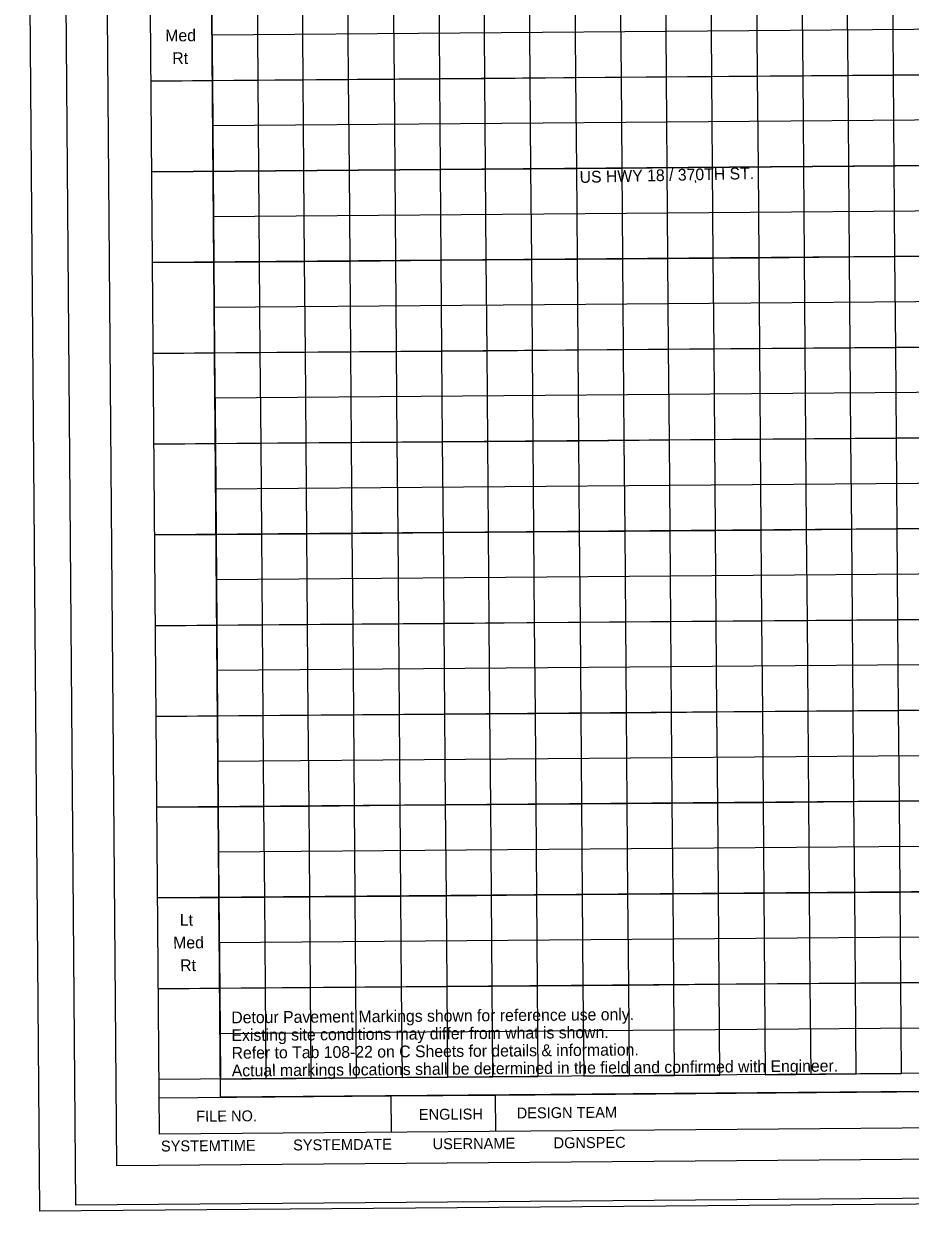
# Model space of a CAD drawing. Extents: x 11670159 to 11702568, y 9558247 to 9571922.
# Drawn here: x 11683828 to 11685781, y 9566402 to 9569018 of the extents above; entities that cross this region are included whole.
import ezdxf

# ---------------------------------------------------------------- set-up
doc = ezdxf.new("R2010")
doc.units = 0
for name, color, linetype in [('dsnNonPlotable', 7, 'Continuous'), ('DsnShtDBGLtRtTextLower', 7, 'Continuous'), ('DsnShtDBGLtRtTextUpper', 7, 'Continuous'), ('DsnShtDBGMedTextLower', 7, 'Continuous'), ('DsnShtDBGMedTextUpper', 7, 'Continuous'), ('DsnShtHorizMidLine', 7, 'Continuous'), ('DsnShtInsideBorder', 7, 'Continuous'), ('DsnShtMajorGrid01', 7, 'Continuous'), ('DsnShtMajorGrid02', 7, 'Continuous'), ('DsnShtMajorGrid03', 7, 'Continuous'), ('DsnShtMajorGrid04', 7, 'Continuous'), ('DsnShtMajorGrid05', 7, 'Continuous'), ('DsnShtMajorGrid06', 7, 'Continuous'), ('DsnShtMajorGrid07', 7, 'Continuous'), ('DsnShtMajorGrid08', 7, 'Continuous'), ('DsnShtMajorGrid09', 7, 'Continuous'), ('DsnShtMajorGrid10', 7, 'Continuous'), ('DsnShtMajorGrid11', 7, 'Continuous'), ('DsnShtMajorGrid12', 7, 'Continuous'), ('DsnShtMinorGrid01', 7, 'Continuous'), ('DsnShtMinorGrid02', 7, 'Continuous'), ('DsnShtMinorGrid03', 7, 'Continuous'), ('DsnShtMinorGrid04', 7, 'Continuous'), ('DsnShtMinorGrid05', 7, 'Continuous'), ('DsnShtMinorGrid06', 7, 'Continuous'), ('DsnShtMinorGrid07', 7, 'Continuous'), ('DsnShtMinorGrid08', 7, 'Continuous'), ('DsnShtMinorGrid09', 7, 'Continuous'), ('DsnShtMinorGrid10', 7, 'Continuous'), ('DsnShtMinorGrid11', 7, 'Continuous'), ('DsnShtMinorGrid12', 7, 'Continuous'), ('DsnShtOutsideBorder', 7, 'Continuous'), ('DsnShtPlotIdentification', 7, 'Continuous'), ('DsnShtPlotShape', 7, 'Continuous'), ('dsnShtPlotShapeBatchPrint', 7, 'Continuous'), ('dsnTextFinalPlan', 7, 'Continuous'), ('hwyPlanSheetShape', 7, 'Continuous')]:
    doc.layers.add(name, color=color, linetype=linetype)

msp = doc.modelspace()

# ---------------------------------------------------------------- linework, layer by layer
at = {"layer": 'dsnNonPlotable'}
msp.add_line((11685307.4, 9568673.2), (11685307.5, 9568668.3), dxfattribs=at)
msp.add_lwpolyline([(11684229.4, 9570693), (11690229.2, 9570741.4), (11690261.8, 9566701.6), (11684262, 9566653.2)], close=True, dxfattribs=at)
at = {"layer": 'DsnShtHorizMidLine'}
msp.add_line((11684110.5, 9568692), (11690380.3, 9568742.6), dxfattribs=at)
at = {"layer": 'DsnShtInsideBorder'}
for p, q in [((11684636.8, 9566656.2), (11684637.4, 9566576.2)), ((11684866.8, 9566658), (11684867.4, 9566578))]:
    msp.add_line(p, q, dxfattribs=at)
at = {"layer": 'DsnShtMajorGrid01'}
for points in [[(11690394.8, 9566942.6), (11684125, 9566892.1), (11684260, 9566893.1), (11684261.7, 9566693.2), (11684461.6, 9566694.8), (11684460, 9566894.8), (11684660, 9566896.4), (11684661.6, 9566696.4), (11684861.6, 9566698), (11684860, 9566898), (11685060, 9566899.6), (11685061.6, 9566699.6), (11685261.6, 9566701.2), (11685260, 9566901.2), (11685460, 9566902.8), (11685461.6, 9566702.8), (11685661.6, 9566704.4), (11685660, 9566904.4), (11685860, 9566906.1)], [(11690396.5, 9566742.6), (11684126.7, 9566692.1)]]:
    msp.add_lwpolyline(points, dxfattribs=at)
at = {"layer": 'DsnShtMajorGrid02'}
for points in [[(11690393.2, 9567142.6), (11684123.4, 9567092.1), (11684258.4, 9567093.1), (11684260, 9566893.1), (11684460, 9566894.8), (11684458.4, 9567094.8), (11684658.4, 9567096.4), (11684660, 9566896.4), (11684860, 9566898), (11684858.4, 9567098), (11685058.4, 9567099.6), (11685060, 9566899.6), (11685260, 9566901.2), (11685258.4, 9567101.2), (11685458.4, 9567102.8), (11685460, 9566902.8), (11685660, 9566904.4), (11685658.4, 9567104.4), (11685858.4, 9567106)], [(11690394.8, 9566942.6), (11684125, 9566892.1)]]:
    msp.add_lwpolyline(points, dxfattribs=at)
at = {"layer": 'DsnShtMajorGrid03'}
for points in [[(11690391.6, 9567342.6), (11684121.8, 9567292), (11684256.8, 9567293.1), (11684258.4, 9567093.1), (11684458.4, 9567094.8), (11684456.8, 9567294.7), (11684656.8, 9567296.4), (11684658.4, 9567096.4), (11684858.4, 9567098), (11684856.8, 9567298), (11685056.8, 9567299.6), (11685058.4, 9567099.6), (11685258.4, 9567101.2), (11685256.8, 9567301.2), (11685456.8, 9567302.8), (11685458.4, 9567102.8), (11685658.4, 9567104.4), (11685656.8, 9567304.4), (11685856.8, 9567306)], [(11690393.2, 9567142.6), (11684123.4, 9567092.1)]]:
    msp.add_lwpolyline(points, dxfattribs=at)
at = {"layer": 'DsnShtMajorGrid04'}
for points in [[(11690390, 9567542.6), (11684120.2, 9567492), (11684255.2, 9567493.1), (11684256.8, 9567293.1), (11684456.8, 9567294.7), (11684455.2, 9567494.7), (11684655.2, 9567496.4), (11684656.8, 9567296.4), (11684856.8, 9567298), (11684855.2, 9567498), (11685055.2, 9567499.6), (11685056.8, 9567299.6), (11685256.8, 9567301.2), (11685255.2, 9567501.2), (11685455.2, 9567502.8), (11685456.8, 9567302.8), (11685656.8, 9567304.4), (11685655.2, 9567504.4), (11685855.1, 9567506)], [(11690391.6, 9567342.6), (11684121.8, 9567292)]]:
    msp.add_lwpolyline(points, dxfattribs=at)
at = {"layer": 'DsnShtMajorGrid05'}
for points in [[(11690388.4, 9567742.6), (11684118.6, 9567692), (11684253.6, 9567693.1), (11684255.2, 9567493.1), (11684455.2, 9567494.7), (11684453.6, 9567694.7), (11684653.6, 9567696.3), (11684655.2, 9567496.4), (11684855.2, 9567498), (11684853.6, 9567698), (11685053.6, 9567699.6), (11685055.2, 9567499.6), (11685255.2, 9567501.2), (11685253.6, 9567701.2), (11685453.5, 9567702.8), (11685455.2, 9567502.8), (11685655.2, 9567504.4), (11685653.5, 9567704.4), (11685853.5, 9567706)], [(11690390, 9567542.6), (11684120.2, 9567492)]]:
    msp.add_lwpolyline(points, dxfattribs=at)
at = {"layer": 'DsnShtMajorGrid06'}
for points in [[(11690386.8, 9567942.6), (11684117, 9567892), (11684252, 9567893.1), (11684253.6, 9567693.1), (11684453.6, 9567694.7), (11684452, 9567894.7), (11684652, 9567896.3), (11684653.6, 9567696.3), (11684853.6, 9567698), (11684852, 9567898), (11685051.9, 9567899.6), (11685053.6, 9567699.6), (11685253.6, 9567701.2), (11685251.9, 9567901.2), (11685451.9, 9567902.8), (11685453.5, 9567702.8), (11685653.5, 9567704.4), (11685651.9, 9567904.4), (11685851.9, 9567906)], [(11690388.4, 9567742.6), (11684118.6, 9567692)]]:
    msp.add_lwpolyline(points, dxfattribs=at)
at = {"layer": 'DsnShtMajorGrid07'}
for points in [[(11690385.2, 9568142.6), (11684115.4, 9568092), (11684250.4, 9568093.1), (11684252, 9567893.1), (11684452, 9567894.7), (11684450.4, 9568094.7), (11684650.3, 9568096.3), (11684652, 9567896.3), (11684852, 9567898), (11684850.3, 9568097.9), (11685050.3, 9568099.6), (11685051.9, 9567899.6), (11685251.9, 9567901.2), (11685250.3, 9568101.2), (11685450.3, 9568102.8), (11685451.9, 9567902.8), (11685651.9, 9567904.4), (11685650.3, 9568104.4), (11685850.3, 9568106)], [(11690386.8, 9567942.6), (11684117, 9567892)]]:
    msp.add_lwpolyline(points, dxfattribs=at)
at = {"layer": 'DsnShtMajorGrid08'}
for points in [[(11690383.5, 9568342.6), (11684113.7, 9568292), (11684248.7, 9568293.1), (11684250.4, 9568093.1), (11684450.4, 9568094.7), (11684448.7, 9568294.7), (11684648.7, 9568296.3), (11684650.3, 9568096.3), (11684850.3, 9568097.9), (11684848.7, 9568297.9), (11685048.7, 9568299.6), (11685050.3, 9568099.6), (11685250.3, 9568101.2), (11685248.7, 9568301.2), (11685448.7, 9568302.8), (11685450.3, 9568102.8), (11685650.3, 9568104.4), (11685648.7, 9568304.4), (11685848.7, 9568306)], [(11690385.2, 9568142.6), (11684115.4, 9568092)]]:
    msp.add_lwpolyline(points, dxfattribs=at)
at = {"layer": 'DsnShtMajorGrid09'}
for points in [[(11690381.9, 9568542.6), (11684112.1, 9568492), (11684247.1, 9568493.1), (11684248.7, 9568293.1), (11684448.7, 9568294.7), (11684447.1, 9568494.7), (11684647.1, 9568496.3), (11684648.7, 9568296.3), (11684848.7, 9568297.9), (11684847.1, 9568497.9), (11685047.1, 9568499.5), (11685048.7, 9568299.6), (11685248.7, 9568301.2), (11685247.1, 9568501.2), (11685447.1, 9568502.8), (11685448.7, 9568302.8), (11685648.7, 9568304.4), (11685647.1, 9568504.4), (11685847.1, 9568506)], [(11690383.5, 9568342.6), (11684113.7, 9568292)]]:
    msp.add_lwpolyline(points, dxfattribs=at)
at = {"layer": 'DsnShtMajorGrid10'}
for points in [[(11690380.3, 9568742.6), (11684110.5, 9568692), (11684245.5, 9568693.1), (11684247.1, 9568493.1), (11684447.1, 9568494.7), (11684445.5, 9568694.7), (11684645.5, 9568696.3), (11684647.1, 9568496.3), (11684847.1, 9568497.9), (11684845.5, 9568697.9), (11685045.5, 9568699.5), (11685047.1, 9568499.5), (11685247.1, 9568501.2), (11685245.5, 9568701.2), (11685445.5, 9568702.8), (11685447.1, 9568502.8), (11685647.1, 9568504.4), (11685645.5, 9568704.4), (11685845.5, 9568706)], [(11690381.9, 9568542.6), (11684112.1, 9568492)]]:
    msp.add_lwpolyline(points, dxfattribs=at)
at = {"layer": 'DsnShtMajorGrid11'}
for points in [[(11690378.7, 9568942.6), (11684108.9, 9568892), (11684243.9, 9568893.1), (11684245.5, 9568693.1), (11684445.5, 9568694.7), (11684443.9, 9568894.7), (11684643.9, 9568896.3), (11684645.5, 9568696.3), (11684845.5, 9568697.9), (11684843.9, 9568897.9), (11685043.9, 9568899.5), (11685045.5, 9568699.5), (11685245.5, 9568701.2), (11685243.9, 9568901.1), (11685443.9, 9568902.8), (11685445.5, 9568702.8), (11685645.5, 9568704.4), (11685643.9, 9568904.4), (11685843.9, 9568906)], [(11690380.3, 9568742.6), (11684110.5, 9568692)]]:
    msp.add_lwpolyline(points, dxfattribs=at)
at = {"layer": 'DsnShtMajorGrid12'}
for points in [[(11685442.3, 9569102.8), (11685443.9, 9568902.8), (11685643.9, 9568904.4), (11685642.2, 9569104.4)], [(11684242.3, 9569093.1), (11684243.9, 9568893.1), (11684443.9, 9568894.7), (11684442.3, 9569094.7)], [(11684642.3, 9569096.3), (11684643.9, 9568896.3), (11684843.9, 9568897.9), (11684842.3, 9569097.9)], [(11685042.3, 9569099.5), (11685043.9, 9568899.5), (11685243.9, 9568901.1), (11685242.3, 9569101.1)], [(11690378.7, 9568942.6), (11684108.9, 9568892)]]:
    msp.add_lwpolyline(points, dxfattribs=at)
at = {"layer": 'DsnShtMinorGrid01'}
msp.add_lwpolyline([(11690260.6, 9566841.5), (11684260.8, 9566793.1), (11684260, 9566893.1), (11684360, 9566894), (11684361.6, 9566694), (11684561.6, 9566695.6), (11684560, 9566895.6), (11684760, 9566897.2), (11684761.6, 9566697.2), (11684961.6, 9566698.8), (11684960, 9566898.8), (11685160, 9566900.4), (11685161.6, 9566700.4), (11685361.6, 9566702), (11685360, 9566902), (11685560, 9566903.6), (11685561.6, 9566703.6), (11685761.6, 9566705.3), (11685760, 9566905.2), (11685960, 9566906.9)], dxfattribs=at)
at = {"layer": 'DsnShtMinorGrid02'}
msp.add_lwpolyline([(11690259, 9567041.5), (11684259.2, 9566993.1), (11684258.4, 9567093.1), (11684358.4, 9567093.9), (11684360, 9566894), (11684560, 9566895.6), (11684558.4, 9567095.6), (11684758.4, 9567097.2), (11684760, 9566897.2), (11684960, 9566898.8), (11684958.4, 9567098.8), (11685158.4, 9567100.4), (11685160, 9566900.4), (11685360, 9566902), (11685358.4, 9567102), (11685558.4, 9567103.6), (11685560, 9566903.6), (11685760, 9566905.2), (11685758.4, 9567105.2), (11685958.4, 9567106.9)], dxfattribs=at)
at = {"layer": 'DsnShtMinorGrid03'}
msp.add_lwpolyline([(11690257.4, 9567241.5), (11684257.6, 9567193.1), (11684256.8, 9567293.1), (11684356.8, 9567293.9), (11684358.4, 9567093.9), (11684558.4, 9567095.6), (11684556.8, 9567295.6), (11684756.8, 9567297.2), (11684758.4, 9567097.2), (11684958.4, 9567098.8), (11684956.8, 9567298.8), (11685156.8, 9567300.4), (11685158.4, 9567100.4), (11685358.4, 9567102), (11685356.8, 9567302), (11685556.8, 9567303.6), (11685558.4, 9567103.6), (11685758.4, 9567105.2), (11685756.8, 9567305.2), (11685956.8, 9567306.8)], dxfattribs=at)
at = {"layer": 'DsnShtMinorGrid04'}
msp.add_lwpolyline([(11690255.8, 9567441.5), (11684256, 9567393.1), (11684255.2, 9567493.1), (11684355.2, 9567493.9), (11684356.8, 9567293.9), (11684556.8, 9567295.6), (11684555.2, 9567495.5), (11684755.2, 9567497.2), (11684756.8, 9567297.2), (11684956.8, 9567298.8), (11684955.2, 9567498.8), (11685155.2, 9567500.4), (11685156.8, 9567300.4), (11685356.8, 9567302), (11685355.2, 9567502), (11685555.2, 9567503.6), (11685556.8, 9567303.6), (11685756.8, 9567305.2), (11685755.1, 9567505.2), (11685955.1, 9567506.8)], dxfattribs=at)
at = {"layer": 'DsnShtMinorGrid05'}
msp.add_lwpolyline([(11690254.2, 9567641.5), (11684254.4, 9567593.1), (11684253.6, 9567693.1), (11684353.6, 9567693.9), (11684355.2, 9567493.9), (11684555.2, 9567495.5), (11684553.6, 9567695.5), (11684753.6, 9567697.2), (11684755.2, 9567497.2), (11684955.2, 9567498.8), (11684953.6, 9567698.8), (11685153.6, 9567700.4), (11685155.2, 9567500.4), (11685355.2, 9567502), (11685353.5, 9567702), (11685553.5, 9567703.6), (11685555.2, 9567503.6), (11685755.1, 9567505.2), (11685753.5, 9567705.2), (11685953.5, 9567706.8)], dxfattribs=at)
at = {"layer": 'DsnShtMinorGrid06'}
msp.add_lwpolyline([(11690252.6, 9567841.5), (11684252.8, 9567793.1), (11684252, 9567893.1), (11684352, 9567893.9), (11684353.6, 9567693.9), (11684553.6, 9567695.5), (11684552, 9567895.5), (11684752, 9567897.1), (11684753.6, 9567697.2), (11684953.6, 9567698.8), (11684951.9, 9567898.8), (11685151.9, 9567900.4), (11685153.6, 9567700.4), (11685353.5, 9567702), (11685351.9, 9567902), (11685551.9, 9567903.6), (11685553.5, 9567703.6), (11685753.5, 9567705.2), (11685751.9, 9567905.2), (11685951.9, 9567906.8)], dxfattribs=at)
at = {"layer": 'DsnShtMinorGrid07'}
msp.add_lwpolyline([(11690251, 9568041.5), (11684251.2, 9567993.1), (11684250.4, 9568093.1), (11684350.4, 9568093.9), (11684352, 9567893.9), (11684552, 9567895.5), (11684550.3, 9568095.5), (11684750.3, 9568097.1), (11684752, 9567897.1), (11684951.9, 9567898.8), (11684950.3, 9568098.8), (11685150.3, 9568100.4), (11685151.9, 9567900.4), (11685351.9, 9567902), (11685350.3, 9568102), (11685550.3, 9568103.6), (11685551.9, 9567903.6), (11685751.9, 9567905.2), (11685750.3, 9568105.2), (11685950.3, 9568106.8)], dxfattribs=at)
at = {"layer": 'DsnShtMinorGrid08'}
msp.add_lwpolyline([(11690249.4, 9568241.5), (11684249.6, 9568193.1), (11684248.7, 9568293.1), (11684348.7, 9568293.9), (11684350.4, 9568093.9), (11684550.3, 9568095.5), (11684548.7, 9568295.5), (11684748.7, 9568297.1), (11684750.3, 9568097.1), (11684950.3, 9568098.8), (11684948.7, 9568298.7), (11685148.7, 9568300.4), (11685150.3, 9568100.4), (11685350.3, 9568102), (11685348.7, 9568302), (11685548.7, 9568303.6), (11685550.3, 9568103.6), (11685750.3, 9568105.2), (11685748.7, 9568305.2), (11685948.7, 9568306.8)], dxfattribs=at)
at = {"layer": 'DsnShtMinorGrid09'}
msp.add_lwpolyline([(11690247.7, 9568441.5), (11684247.9, 9568393.1), (11684247.1, 9568493.1), (11684347.1, 9568493.9), (11684348.7, 9568293.9), (11684548.7, 9568295.5), (11684547.1, 9568495.5), (11684747.1, 9568497.1), (11684748.7, 9568297.1), (11684948.7, 9568298.7), (11684947.1, 9568498.7), (11685147.1, 9568500.4), (11685148.7, 9568300.4), (11685348.7, 9568302), (11685347.1, 9568502), (11685547.1, 9568503.6), (11685548.7, 9568303.6), (11685748.7, 9568305.2), (11685747.1, 9568505.2), (11685947.1, 9568506.8)], dxfattribs=at)
at = {"layer": 'DsnShtMinorGrid10'}
msp.add_lwpolyline([(11690246.1, 9568641.5), (11684246.3, 9568593.1), (11684245.5, 9568693.1), (11684345.5, 9568693.9), (11684347.1, 9568493.9), (11684547.1, 9568495.5), (11684545.5, 9568695.5), (11684745.5, 9568697.1), (11684747.1, 9568497.1), (11684947.1, 9568498.7), (11684945.5, 9568698.7), (11685145.5, 9568700.3), (11685147.1, 9568500.4), (11685347.1, 9568502), (11685345.5, 9568702), (11685545.5, 9568703.6), (11685547.1, 9568503.6), (11685747.1, 9568505.2), (11685745.5, 9568705.2), (11685945.5, 9568706.8)], dxfattribs=at)
at = {"layer": 'DsnShtMinorGrid11'}
msp.add_lwpolyline([(11690244.5, 9568841.5), (11684244.7, 9568793.1), (11684243.9, 9568893.1), (11684343.9, 9568893.9), (11684345.5, 9568693.9), (11684545.5, 9568695.5), (11684543.9, 9568895.5), (11684743.9, 9568897.1), (11684745.5, 9568697.1), (11684945.5, 9568698.7), (11684943.9, 9568898.7), (11685143.9, 9568900.3), (11685145.5, 9568700.3), (11685345.5, 9568702), (11685343.9, 9568902), (11685543.9, 9568903.6), (11685545.5, 9568703.6), (11685745.5, 9568705.2), (11685743.9, 9568905.2), (11685943.8, 9568906.8)], dxfattribs=at)
at = {"layer": 'DsnShtMinorGrid12'}
for points in [[(11685142.3, 9569100.3), (11685143.9, 9568900.3), (11685343.9, 9568902), (11685342.3, 9569101.9)], [(11685542.2, 9569103.6), (11685543.9, 9568903.6), (11685743.9, 9568905.2), (11685742.2, 9569105.2)], [(11690242.9, 9569041.5), (11684243.1, 9568993.1), (11684242.3, 9569093.1)], [(11684342.3, 9569093.9), (11684343.9, 9568893.9), (11684543.9, 9568895.5), (11684542.3, 9569095.5)], [(11684742.3, 9569097.1), (11684743.9, 9568897.1), (11684943.9, 9568898.7), (11684942.3, 9569098.7)]]:
    msp.add_lwpolyline(points, dxfattribs=at)
at = {"layer": 'DsnShtOutsideBorder'}
for p, q in [((11684866.8, 9566658), (11687859.9, 9566682.2)), ((11684127, 9566652.1), (11684636.8, 9566656.2)), ((11684636.8, 9566656.2), (11684866.8, 9566658)), ((11684636.8, 9566656.2), (11684637.4, 9566576.2)), ((11684866.8, 9566658), (11684867.4, 9566578))]:
    msp.add_line(p, q, dxfattribs=at)
msp.add_lwpolyline([(11684094.4, 9570691.9), (11690364.2, 9570742.5), (11690397.4, 9566622.6), (11684127.6, 9566572.1)], close=True, dxfattribs=at)
at = {"layer": 'DsnShtPlotShape'}
msp.add_lwpolyline([(11683828.5, 9570801.8), (11690628.3, 9570856.6), (11690663.8, 9566456.8), (11683864, 9566401.9)], close=True, dxfattribs=at)
at = {"layer": 'dsnShtPlotShapeBatchPrint'}
msp.add_lwpolyline([(11683907.6, 9570802.4), (11690549.2, 9570856), (11690584.6, 9566469.3), (11683943, 9566415.7)], close=True, dxfattribs=at)
at = {"layer": 'hwyPlanSheetShape'}
msp.add_lwpolyline([(11683998.8, 9570760.1), (11690458.6, 9570812.2), (11690493, 9566554), (11684033.2, 9566501.9)], close=True, dxfattribs=at)

# ---------------------------------------------------------------- texts
at = {"layer": 'DsnShtDBGLtRtTextLower'}
for s, p in [('Lt', (11684172.3, 9567030.8)), ('Rt', (11684173.1, 9566930.8))]:
    msp.add_text(s, height=26, rotation=0.4622, dxfattribs=at).set_placement(p)
at = {"layer": 'DsnShtDBGLtRtTextUpper'}
msp.add_text('Rt', height=26, rotation=0.4622, dxfattribs=at).set_placement((11684155.6, 9568929.4))
at = {"layer": 'DsnShtDBGMedTextLower'}
msp.add_text('Med', height=26, rotation=0.4622, dxfattribs=at).set_placement((11684157.7, 9566980.7))
at = {"layer": 'DsnShtDBGMedTextUpper'}
msp.add_text('Med', height=26, rotation=0.4622, dxfattribs=at).set_placement((11684140.2, 9568979.2))
at = {"layer": 'DsnShtInsideBorder'}
for s, p in [('FILE NO.', (11684208.4, 9566599.2)), ('ENGLISH', (11684698.8, 9566603.2)), ('DESIGN TEAM', (11684914.2, 9566606.4))]:
    msp.add_text(s, height=24, rotation=0.4622, dxfattribs=at).set_placement(p)
at = {"layer": 'DsnShtPlotIdentification'}
for s, p in [('DGNSPEC', (11684995.4, 9566540.5)), ('SYSTEMTIME', (11684130.7, 9566533.5)), ('SYSTEMDATE', (11684421.8, 9566535.9)), ('USERNAME', (11684729, 9566538.4))]:
    msp.add_text(s, height=24, rotation=0.4622, dxfattribs=at).set_placement(p)
at = {"layer": 'dsnTextFinalPlan'}
for s, rotation, p in [('US HWY 18 / 370TH ST.', 1.2977, (11685052.9, 9568667.4)), ('Detour Pavement Markings shown for reference use only.', 0.4622, (11684285.7, 9566815.9)), ('Existing site conditions may differ from what is shown.', 0.4622, (11684286, 9566776.9)), ('Refer to Tab 108-22 on C Sheets for details & information.', 0.4622, (11684286.3, 9566737.9)), ('Actual markings locations shall be determined in the field and confirmed with Engineer.', 0.4622, (11684286.6, 9566698.9))]:
    msp.add_text(s, height=26, rotation=rotation, dxfattribs=at).set_placement(p)

doc.saveas('drawing.dxf')
